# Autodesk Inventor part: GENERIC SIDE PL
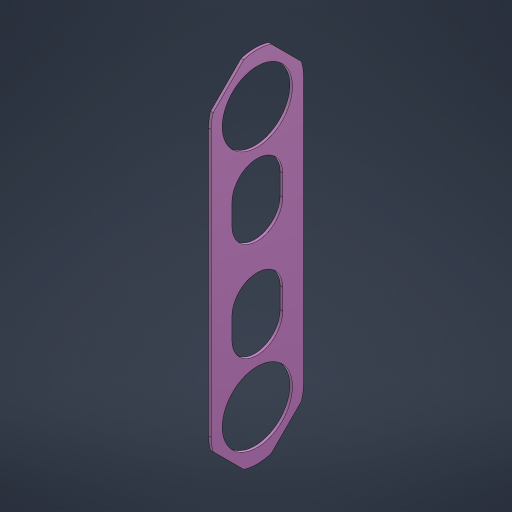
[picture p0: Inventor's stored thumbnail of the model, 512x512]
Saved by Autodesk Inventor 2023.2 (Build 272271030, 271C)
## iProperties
Created: 2023-04
Part Number: GENERIC SIDE PL
Material: Generic
Document SubType Name: Modeling
Designer: AR
Mass: 19.8727 g
Surface Area: 224.25 cm^2
Volume: 19.8727 cm^3
Density: 1 g/cm^3
Appearance: Default
Author: AR
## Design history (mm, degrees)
derived "_2 SPOOL CORD WRAP MP.ipt"
workaxis "Work Axis1"
  workplane "Work Plane1"
feature "GENERIC SIDE PL::_2 SPOOL CORD WRAP MP.ipt" dims "d0" = 10
tag "TaggingFeature1"
node "GENERIC SIDE PL"
